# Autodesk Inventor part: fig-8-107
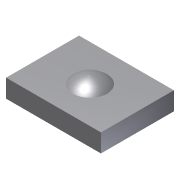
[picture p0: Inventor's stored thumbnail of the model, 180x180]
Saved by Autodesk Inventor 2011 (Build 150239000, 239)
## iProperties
Created: 2009-09
Part Number: fig-8-107
Document SubType Name: Modeling
Designer: Sham
Density: 1 g/cm^3
Author: Sham
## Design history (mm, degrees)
sketch "Sketch1"
  geometry: L1 (-26, 20)-(0, 20); L2 (0, 20)-(0, 0); L3 (0, 0)-(-26, 0); L4 (-26, 0)-(-26, 20)
  constraints: 8 end point, 2 parallel, 1 horizontal, 1 perpendicular
extrude "Extrusion1" new body sketch "Sketch1" distance "d0" = 5; taper "d1" = 0 deg
workplane "Work Plane1"
feature "Sculpt2"
body "Solid1"
sketch "Sketch2"
  geometry: L1 (13, 8)-(13, 5); A1 r 7.517 centre (12.377, -0.349) between (17.658, 5) and (13, 7.142)
  constraints: 2 end point, 2 point on circle, 1 centre point
body "Srf2"
feature "RevolutionSrf2" dims angle "d4" = 90 deg
